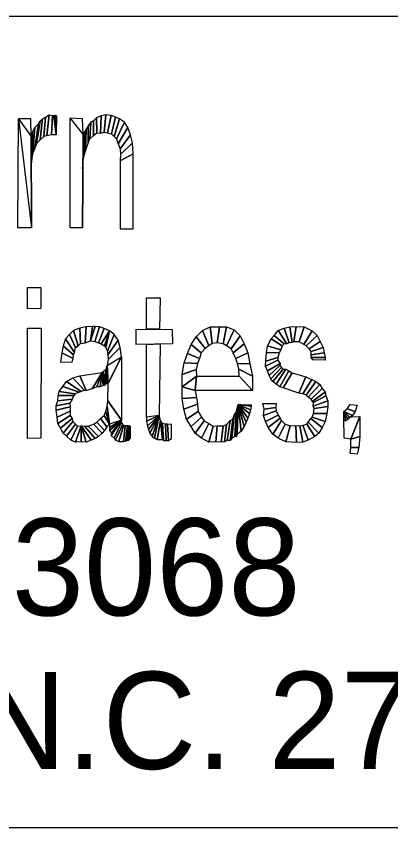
# Model space of a CAD drawing. Extents: x 578158 to 582505, y -54320 to -53220.
# Drawn here: x 579757.4 to 579778.85, y -53316.14 to -53269.66 of the extents above; entities that cross this region are included whole.
import ezdxf

# ---------------------------------------------------------------- set-up
doc = ezdxf.new("R2010")
doc.units = 0
for name, color, linetype in [('Old_Level_2', 7, 'Continuous'), ('Sheet Profile CELL', 7, 'Continuous'), ('Sheet Summary CELL', 7, 'Continuous')]:
    doc.layers.add(name, color=color, linetype=linetype)

msp = doc.modelspace()

# ---------------------------------------------------------------- linework, layer by layer
at = {"layer": 'Old_Level_2'}
for points in [[(579758.978, -53276.554), (579759.068, -53275.443), (579759.278, -53275.308), (579759.142, -53276.509)], [(579759.142, -53276.509), (579759.278, -53275.308), (579759.473, -53275.353), (579759.413, -53276.449)], [(579759.413, -53276.449), (579759.473, -53275.353), (579759.548, -53275.353), (579759.682, -53276.449)], [(579759.682, -53276.449), (579759.548, -53275.353), (579759.653, -53275.323), (579759.682, -53276.449)], [(579759.682, -53276.449), (579759.653, -53275.323), (579759.698, -53275.369), (579759.682, -53276.449)], [(579762.218, -53276.359), (579762.263, -53275.369), (579761.993, -53275.488), (579762.008, -53276.343)], [(579762.428, -53276.298), (579762.518, -53275.308), (579762.263, -53275.369), (579762.218, -53276.359)], [(579762.623, -53276.343), (579762.833, -53275.353), (579762.518, -53275.308), (579762.428, -53276.298)], [(579762.848, -53276.403), (579763.073, -53275.443), (579762.833, -53275.353), (579762.623, -53276.343)], [(579757.478, -53281.788), (579757.522, -53275.533), (579758.258, -53276.554), (579758.273, -53281.788)], [(579758.273, -53281.788), (579758.258, -53276.554), (579758.228, -53275.533), (579757.522, -53275.533)], [(579758.348, -53277.483), (579758.453, -53276.043), (579758.663, -53275.834), (579758.453, -53277.214)], [(579758.453, -53277.214), (579758.663, -53275.834), (579758.768, -53275.668), (579758.558, -53276.959)], [(579758.558, -53276.959), (579758.768, -53275.668), (579758.903, -53275.533), (579758.768, -53276.734)], [(579758.768, -53276.734), (579758.903, -53275.533), (579759.068, -53275.443), (579758.978, -53276.554)], [(579760.493, -53281.774), (579760.493, -53275.503), (579761.228, -53276.449), (579761.198, -53281.788)], [(579761.183, -53275.533), (579760.493, -53275.503), (579761.228, -53276.449)], [(579761.603, -53276.689), (579761.662, -53275.729), (579761.513, -53275.938), (579761.513, -53276.928)], [(579761.828, -53276.494), (579761.813, -53275.654), (579761.662, -53275.729), (579761.603, -53276.689)], [(579762.008, -53276.343), (579761.993, -53275.488), (579761.813, -53275.654), (579761.828, -53276.494)], [(579763.013, -53276.554), (579763.313, -53275.533), (579763.073, -53275.443), (579762.848, -53276.403)], [(579763.133, -53276.689), (579763.598, -53275.729), (579763.313, -53275.533), (579763.013, -53276.554)], [(579763.238, -53276.973), (579763.778, -53276.043), (579763.598, -53275.729), (579763.133, -53276.689)], [(579758.258, -53278.174), (579758.258, -53276.554), (579758.333, -53276.298), (579758.288, -53277.769)], [(579758.288, -53277.769), (579758.333, -53276.298), (579758.453, -53276.043), (579758.348, -53277.483)], [(579761.243, -53277.769), (579761.318, -53276.269), (579761.228, -53276.449), (579761.198, -53278.399)], [(579761.363, -53277.378), (579761.408, -53276.134), (579761.318, -53276.269), (579761.243, -53277.769)], [(579761.513, -53276.928), (579761.513, -53275.938), (579761.408, -53276.134), (579761.363, -53277.378)], [(579763.343, -53277.259), (579763.943, -53276.449), (579763.778, -53276.043), (579763.238, -53276.973)], [(579758.258, -53276.554), (579758.258, -53276.554), (579758.258, -53278.174), (579758.273, -53281.788)], [(579761.228, -53276.449), (579761.228, -53276.449), (579761.198, -53278.399), (579761.198, -53281.788)], [(579763.358, -53277.589), (579764.048, -53276.914), (579763.943, -53276.449), (579763.343, -53277.259)], [(579763.343, -53277.949), (579764.093, -53277.543), (579764.048, -53276.914), (579763.358, -53277.589)], [(579763.343, -53281.833), (579764.093, -53281.833), (579764.093, -53277.543), (579763.343, -53277.949)], [(579758.033, -53285.194), (579758.798, -53285.194), (579758.798, -53286.409), (579758.048, -53286.423)], [(579764.858, -53285.793), (579765.638, -53285.793), (579765.608, -53287.593), (579764.858, -53287.593)], [(579761.348, -53288.358), (579761.408, -53287.443), (579761.033, -53287.534), (579761.078, -53288.403)], [(579761.648, -53288.254), (579761.768, -53287.429), (579761.408, -53287.443), (579761.348, -53288.358)], [(579761.888, -53288.299), (579762.158, -53287.443), (579761.918, -53287.429), (579761.648, -53288.254)], [(579761.648, -53288.254), (579761.918, -53287.429), (579761.768, -53287.429), (579761.648, -53288.254)], [(579762.113, -53288.358), (579762.428, -53287.548), (579762.158, -53287.443), (579761.888, -53288.299)], [(579768.502, -53287.458), (579768.608, -53288.403), (579768.428, -53288.538), (579768.068, -53287.669)], [(579769.028, -53287.443), (579768.908, -53288.358), (579768.608, -53288.403), (579768.502, -53287.458)], [(579769.433, -53287.458), (579769.238, -53288.434), (579768.908, -53288.358), (579769.028, -53287.443)], [(579769.868, -53287.623), (579769.433, -53288.538), (579769.238, -53288.434), (579769.433, -53287.458)], [(579773.063, -53287.443), (579773.198, -53288.343), (579773.033, -53288.358), (579772.733, -53287.534)], [(579773.423, -53287.429), (579773.288, -53288.313), (579773.198, -53288.343), (579773.063, -53287.443)], [(579773.888, -53287.458), (579773.603, -53288.313), (579773.288, -53288.313), (579773.423, -53287.429)], [(579774.338, -53287.683), (579773.873, -53288.463), (579773.603, -53288.313), (579773.888, -53287.458)], [(579758.048, -53287.534), (579758.828, -53287.534), (579758.798, -53293.834), (579758.048, -53293.848)], [(579760.793, -53288.643), (579760.448, -53287.894), (579760.222, -53288.133), (579760.733, -53288.929)], [(579760.942, -53288.538), (579760.673, -53287.669), (579760.448, -53287.894), (579760.793, -53288.643)], [(579761.078, -53288.403), (579761.033, -53287.534), (579760.673, -53287.669), (579760.942, -53288.538)], [(579762.263, -53288.434), (579762.728, -53287.683), (579762.428, -53287.548), (579762.113, -53288.358)], [(579762.443, -53288.538), (579762.728, -53287.683), (579762.728, -53287.683), (579762.263, -53288.434)], [(579762.518, -53288.643), (579762.728, -53287.683), (579762.728, -53287.683), (579762.443, -53288.538)], [(579762.623, -53288.853), (579763.013, -53287.894), (579762.728, -53287.683), (579762.518, -53288.643)], [(579762.638, -53289.049), (579763.238, -53288.223), (579763.013, -53287.894), (579762.623, -53288.853)], [(579764.273, -53288.463), (579764.273, -53287.593), (579766.328, -53287.609), (579766.342, -53288.434)], [(579768.068, -53287.669), (579768.428, -53288.538), (579768.218, -53288.689), (579767.708, -53288.029)], [(579770.213, -53287.969), (579769.703, -53288.703), (579769.433, -53288.538), (579769.868, -53287.623)], [(579772.163, -53287.939), (579772.733, -53288.434), (579772.628, -53288.538), (579771.998, -53288.133)], [(579772.403, -53287.669), (579772.898, -53288.434), (579772.733, -53288.434), (579772.163, -53287.939)], [(579772.733, -53287.534), (579773.033, -53288.358), (579772.898, -53288.434), (579772.403, -53287.669)], [(579774.622, -53287.953), (579774.008, -53288.538), (579773.873, -53288.463), (579774.338, -53287.683)], [(579760.733, -53288.929), (579760.222, -53288.133), (579760.088, -53288.538), (579760.673, -53289.049)], [(579762.668, -53289.319), (579763.343, -53288.643), (579763.238, -53288.223), (579762.638, -53289.049)], [(579767.708, -53288.029), (579768.218, -53288.689), (579767.993, -53288.943), (579767.408, -53288.463)], [(579770.453, -53288.434), (579769.823, -53288.943), (579769.703, -53288.703), (579770.213, -53287.969)], [(579771.998, -53288.133), (579772.628, -53288.538), (579772.553, -53288.763), (579771.788, -53288.538)], [(579774.802, -53288.299), (579774.173, -53288.703), (579774.008, -53288.538), (579774.622, -53287.953)], [(579774.982, -53288.643), (579774.278, -53288.869), (579774.173, -53288.703), (579774.802, -53288.299)], [(579760.673, -53289.049), (579760.088, -53288.538), (579759.998, -53288.943), (579760.658, -53289.258)], [(579762.608, -53289.663), (579763.418, -53289.168), (579763.343, -53288.643), (579762.668, -53289.319)], [(579764.858, -53288.463), (579765.638, -53288.434), (579765.578, -53292.529), (579764.858, -53292.633)], [(579767.408, -53288.463), (579767.993, -53288.943), (579767.888, -53289.258), (579767.198, -53288.974)], [(579770.662, -53288.943), (579769.973, -53289.274), (579769.823, -53288.943), (579770.453, -53288.434)], [(579771.788, -53288.538), (579772.553, -53288.763), (579772.448, -53288.943), (579771.728, -53288.929)], [(579775.028, -53288.943), (579774.293, -53289.049), (579774.278, -53288.869), (579774.982, -53288.643)], [(579760.658, -53289.258), (579759.998, -53288.943), (579759.938, -53289.483), (579760.598, -53289.454)], [(579762.668, -53290.683), (579762.608, -53289.663), (579763.418, -53289.168)], [(579763.433, -53292.799), (579762.638, -53291.688), (579762.668, -53290.683), (579763.418, -53289.168)], [(579767.198, -53288.974), (579767.888, -53289.258), (579767.768, -53289.559), (579767.018, -53289.514)], [(579770.783, -53289.573), (579770.063, -53289.559), (579769.973, -53289.274), (579770.662, -53288.943)], [(579771.698, -53289.423), (579772.373, -53289.213), (579772.373, -53289.363), (579771.668, -53289.708)], [(579771.728, -53288.929), (579772.448, -53288.943), (579772.373, -53289.213), (579771.698, -53289.423)], [(579775.088, -53289.213), (579774.293, -53289.213), (579774.293, -53289.049), (579775.028, -53288.943)], [(579775.088, -53289.363), (579774.383, -53289.334), (579774.293, -53289.213), (579775.088, -53289.213)], [(579762.608, -53290.683), (579762.548, -53289.874), (579762.608, -53289.663), (579762.668, -53290.683)], [(579767.018, -53289.514), (579767.768, -53289.559), (579767.708, -53289.888), (579766.898, -53290.174)], [(579770.918, -53290.279), (579770.153, -53289.874), (579770.063, -53289.559), (579770.783, -53289.573)], [(579771.668, -53289.708), (579772.373, -53289.363), (579772.508, -53289.559), (579771.788, -53289.963)], [(579771.788, -53289.963), (579772.508, -53289.559), (579772.493, -53289.663), (579771.878, -53290.234)], [(579771.878, -53290.234), (579772.493, -53289.663), (579772.583, -53289.783), (579771.983, -53290.428)], [(579771.983, -53290.428), (579772.583, -53289.783), (579772.688, -53289.874), (579772.088, -53290.579)], [(579761.302, -53291.089), (579760.628, -53290.369), (579761.033, -53290.248), (579761.408, -53291.089)], [(579761.408, -53291.089), (579761.033, -53290.248), (579762.323, -53290.068), (579761.753, -53290.999)], [(579761.753, -53290.999), (579762.323, -53290.068), (579762.323, -53290.068), (579762.008, -53290.878)], [(579762.008, -53290.878), (579762.323, -53290.068), (579762.323, -53290.068), (579762.202, -53290.878)], [(579762.202, -53290.878), (579762.323, -53290.068), (579762.323, -53290.068), (579762.368, -53290.819)], [(579762.368, -53290.819), (579762.323, -53290.068), (579762.398, -53289.994), (579762.458, -53290.803)], [(579762.458, -53290.803), (579762.398, -53289.994), (579762.548, -53289.874), (579762.458, -53290.803)], [(579762.458, -53290.803), (579762.548, -53289.874), (579762.548, -53289.874), (579762.518, -53290.743)], [(579762.518, -53290.743), (579762.548, -53289.874), (579762.548, -53289.874), (579762.608, -53290.683)], [(579766.898, -53290.174), (579767.708, -53289.888), (579767.723, -53290.279), (579766.898, -53290.878)], [(579770.918, -53291.103), (579770.168, -53290.279), (579770.153, -53289.874), (579770.918, -53290.279)], [(579772.088, -53290.579), (579772.688, -53289.874), (579772.838, -53289.874), (579772.282, -53290.743)], [(579772.282, -53290.743), (579772.838, -53289.874), (579773.002, -53289.963), (579772.493, -53290.894)], [(579772.493, -53290.894), (579773.002, -53289.963), (579773.198, -53290.083), (579772.688, -53290.939)], [(579772.688, -53290.939), (579773.198, -53290.083), (579773.978, -53290.309), (579773.588, -53291.254)], [(579761.003, -53291.193), (579760.058, -53290.863), (579760.283, -53290.579), (579761.108, -53291.148)], [(579761.108, -53291.148), (579760.283, -53290.579), (579760.628, -53290.369), (579761.302, -53291.089)], [(579766.898, -53290.878), (579767.723, -53290.279), (579767.648, -53291.089)], [(579767.648, -53291.089), (579767.723, -53290.279), (579770.168, -53290.279), (579770.918, -53291.103)], [(579773.588, -53291.254), (579773.978, -53290.309), (579774.323, -53290.473), (579773.813, -53291.283)], [(579773.813, -53291.283), (579774.323, -53290.473), (579774.563, -53290.579), (579774.008, -53291.373)], [(579774.008, -53291.373), (579774.563, -53290.579), (579774.788, -53290.759), (579774.113, -53291.479)], [(579760.688, -53291.389), (579759.803, -53291.389), (579759.862, -53291.148), (579760.778, -53291.283)], [(579760.778, -53291.283), (579759.862, -53291.148), (579760.058, -53290.863), (579761.003, -53291.193)], [(579766.898, -53290.878), (579767.648, -53291.089), (579767.723, -53291.494), (579766.898, -53291.553)], [(579774.113, -53291.479), (579774.788, -53290.759), (579774.908, -53290.983), (579774.278, -53291.598)], [(579774.278, -53291.598), (579774.908, -53290.983), (579775.088, -53291.193), (579774.353, -53291.719)], [(579774.353, -53291.719), (579775.088, -53291.193), (579775.133, -53291.403), (579774.413, -53291.794)], [(579760.463, -53291.823), (579759.682, -53291.974), (579759.773, -53291.688), (579760.598, -53291.598)], [(579760.598, -53291.598), (579759.773, -53291.688), (579759.803, -53291.389), (579760.688, -53291.389)], [(579766.898, -53291.553), (579767.723, -53291.494), (579767.768, -53291.883), (579767.003, -53292.169)], [(579774.413, -53291.794), (579775.133, -53291.403), (579775.238, -53291.688), (579774.398, -53292.003)], [(579760.493, -53292.034), (579759.682, -53292.228), (579759.682, -53291.974), (579760.463, -53291.823)], [(579760.493, -53292.289), (579759.743, -53292.619), (579759.682, -53292.228), (579760.493, -53292.034)], [(579762.608, -53292.019), (579762.728, -53293.023), (579762.728, -53293.023), (579762.518, -53292.303)], [(579762.638, -53291.688), (579763.433, -53292.799), (579762.728, -53293.023), (579762.608, -53292.019)], [(579767.003, -53292.169), (579767.768, -53291.883), (579767.813, -53292.303), (579767.138, -53292.739)], [(579769.913, -53293.729), (579769.988, -53292.334), (579770.048, -53292.109), (579769.988, -53293.743)], [(579769.988, -53293.743), (579770.048, -53292.109), (579770.108, -53291.899), (579770.048, -53293.609)], [(579770.048, -53293.609), (579770.108, -53291.899), (579770.108, -53291.899), (579770.273, -53293.429)], [(579770.842, -53292.003), (579770.108, -53291.899), (579770.108, -53291.899), (579770.858, -53291.913)], [(579770.813, -53292.199), (579770.108, -53291.899), (579770.108, -53291.899), (579770.842, -53292.003)], [(579770.753, -53292.408), (579770.108, -53291.899), (579770.108, -53291.899), (579770.813, -53292.199)], [(579770.662, -53292.678), (579770.108, -53291.899), (579770.108, -53291.899), (579770.753, -53292.408)], [(579770.573, -53292.919), (579770.108, -53291.899), (579770.108, -53291.899), (579770.662, -53292.678)], [(579770.453, -53293.159), (579770.108, -53291.899), (579770.108, -53291.899), (579770.573, -53292.919)], [(579770.273, -53293.429), (579770.108, -53291.899), (579770.108, -53291.899), (579770.453, -53293.159)], [(579772.268, -53292.063), (579771.593, -53292.169), (579771.518, -53291.839), (579772.282, -53291.839)], [(579772.282, -53292.259), (579771.548, -53292.529), (579771.593, -53292.169), (579772.268, -53292.063)], [(579774.398, -53292.003), (579775.238, -53291.688), (579775.238, -53292.019), (579774.458, -53292.123)], [(579774.458, -53292.123), (579775.238, -53292.019), (579775.178, -53292.408), (579774.413, -53292.423)], [(579776.513, -53291.899), (579776.918, -53291.929), (579776.798, -53292.303), (579776.348, -53292.138)], [(579760.493, -53292.529), (579759.773, -53292.979), (579759.743, -53292.619), (579760.493, -53292.289)], [(579760.598, -53292.709), (579759.938, -53293.263), (579759.773, -53292.979), (579760.493, -53292.529)], [(579762.428, -53292.529), (579762.728, -53293.023), (579762.578, -53293.173), (579762.218, -53292.709)], [(579762.518, -53292.303), (579762.728, -53293.023), (579762.728, -53293.023), (579762.428, -53292.529)], [(579764.918, -53293.114), (579765.578, -53292.529), (579765.578, -53292.529), (579764.858, -53292.858)], [(579764.858, -53292.858), (579765.578, -53292.529), (579765.578, -53292.529), (579764.858, -53292.633)], [(579764.963, -53293.323), (579765.578, -53292.529), (579765.578, -53292.529), (579764.918, -53293.114)], [(579765.038, -53293.549), (579765.578, -53292.529), (579765.578, -53292.529), (579764.963, -53293.323)], [(579765.188, -53293.729), (579765.578, -53292.529), (579765.578, -53292.529), (579765.038, -53293.549)], [(579765.323, -53293.834), (579765.578, -53292.529), (579765.578, -53292.529), (579765.188, -53293.729)], [(579765.473, -53293.909), (579765.653, -53292.813), (579765.578, -53292.529), (579765.323, -53293.834)], [(579767.138, -53292.739), (579767.813, -53292.303), (579768.008, -53292.619), (579767.408, -53293.159)], [(579769.643, -53293.954), (579769.808, -53292.739), (579769.883, -53292.514), (579769.748, -53293.834)], [(579769.748, -53293.834), (579769.883, -53292.514), (579769.988, -53292.334), (579769.913, -53293.729)], [(579772.388, -53292.514), (579771.668, -53292.874), (579771.548, -53292.529), (579772.282, -53292.259)], [(579772.508, -53292.678), (579771.833, -53293.218), (579771.668, -53292.874), (579772.388, -53292.514)], [(579774.413, -53292.423), (579775.178, -53292.408), (579775.088, -53292.874), (579774.353, -53292.619)], [(579776.348, -53292.138), (579776.798, -53292.303), (579776.663, -53292.529), (579776.153, -53292.303)], [(579776.153, -53292.303), (579776.663, -53292.529), (579776.498, -53292.649), (579776.153, -53292.303)], [(579776.153, -53292.303), (579776.498, -53292.649), (579776.378, -53292.754), (579776.153, -53292.303)], [(579776.153, -53292.303), (579776.378, -53292.754), (579776.273, -53292.843), (579776.153, -53292.303)], [(579776.153, -53292.303), (579776.273, -53292.843), (579776.153, -53292.843), (579776.153, -53292.303)], [(579776.153, -53292.619), (579777.083, -53292.588), (579776.558, -53293.879), (579776.168, -53293.834)], [(579776.558, -53293.879), (579777.083, -53292.588), (579777.068, -53293.729)], [(579760.628, -53292.874), (579760.088, -53293.549), (579759.938, -53293.263), (579760.598, -53292.709)], [(579760.793, -53293.023), (579760.283, -53293.713), (579760.088, -53293.549), (579760.628, -53292.874)], [(579760.898, -53293.143), (579760.523, -53293.938), (579760.283, -53293.713), (579760.793, -53293.023)], [(579761.813, -53293.023), (579762.323, -53293.533), (579762.113, -53293.729), (579761.513, -53293.143)], [(579762.008, -53292.919), (579762.458, -53293.383), (579762.323, -53293.533), (579761.813, -53293.023)], [(579762.218, -53292.709), (579762.578, -53293.173), (579762.458, -53293.383), (579762.008, -53292.919)], [(579762.848, -53293.533), (579763.433, -53292.799), (579763.433, -53292.799), (579762.728, -53293.383)], [(579762.728, -53293.218), (579763.433, -53292.799), (579763.433, -53292.799), (579762.728, -53293.023)], [(579762.728, -53293.383), (579763.433, -53292.799), (579763.433, -53292.799), (579762.728, -53293.218)], [(579762.833, -53293.668), (579763.433, -53292.799), (579763.433, -53292.799), (579762.848, -53293.533)], [(579762.998, -53293.834), (579763.418, -53292.919), (579763.433, -53292.799), (579762.833, -53293.668)], [(579763.088, -53293.938), (579763.493, -53293.023), (579763.418, -53292.919), (579762.998, -53293.834)], [(579763.268, -53294.014), (579763.538, -53293.114), (579763.493, -53293.023), (579763.088, -53293.938)], [(579765.773, -53293.909), (579765.653, -53292.813), (579765.653, -53292.813), (579765.473, -53293.909)], [(579765.833, -53293.954), (579765.773, -53292.979), (579765.653, -53292.813), (579765.773, -53293.909)], [(579765.982, -53293.954), (579765.938, -53293.023), (579765.773, -53292.979), (579765.833, -53293.954)], [(579766.118, -53293.954), (579766.058, -53293.023), (579765.938, -53293.023), (579765.982, -53293.954)], [(579766.283, -53293.848), (579766.283, -53293.038), (579766.058, -53293.023), (579766.118, -53293.954)], [(579767.408, -53293.159), (579768.008, -53292.619), (579768.158, -53292.829), (579767.648, -53293.533)], [(579767.648, -53293.533), (579768.158, -53292.829), (579768.428, -53292.979), (579768.008, -53293.834)], [(579768.008, -53293.834), (579768.428, -53292.979), (579768.682, -53293.143), (579768.428, -53294.059)], [(579769.133, -53294.059), (579769.238, -53293.114), (579769.433, -53293.038), (579769.328, -53294.028)], [(579769.328, -53294.028), (579769.433, -53293.038), (579769.643, -53292.813), (579769.478, -53293.954)], [(579769.478, -53293.954), (579769.643, -53292.813), (579769.808, -53292.739), (579769.643, -53293.954)], [(579772.583, -53292.813), (579772.088, -53293.594), (579771.833, -53293.218), (579772.508, -53292.678)], [(579772.793, -53293.023), (579772.388, -53293.834), (579772.088, -53293.594), (579772.583, -53292.813)], [(579773.093, -53293.114), (579772.838, -53294.028), (579772.388, -53293.834), (579772.793, -53293.023)], [(579774.038, -53293.023), (579774.488, -53293.729), (579774.113, -53293.938), (579773.813, -53293.083)], [(579774.113, -53292.919), (579774.728, -53293.533), (579774.488, -53293.729), (579774.038, -53293.023)], [(579774.262, -53292.709), (579774.923, -53293.218), (579774.728, -53293.533), (579774.113, -53292.919)], [(579774.353, -53292.619), (579775.088, -53292.874), (579774.923, -53293.218), (579774.262, -53292.709)], [(579761.108, -53293.114), (579760.793, -53294.059), (579760.523, -53293.938), (579760.898, -53293.143)], [(579761.108, -53293.114), (579761.108, -53294.028), (579760.793, -53294.059), (579761.108, -53293.114)], [(579761.108, -53293.114), (579761.408, -53294.059), (579761.108, -53294.028), (579761.108, -53293.114)], [(579761.108, -53293.114), (579761.693, -53293.938), (579761.408, -53294.059), (579761.108, -53293.114)], [(579761.302, -53293.143), (579761.918, -53293.848), (579761.693, -53293.938), (579761.108, -53293.114)], [(579761.513, -53293.143), (579762.113, -53293.729), (579761.918, -53293.848), (579761.302, -53293.143)], [(579763.538, -53294.014), (579763.642, -53293.114), (579763.538, -53293.114), (579763.268, -53294.014)], [(579763.658, -53293.999), (579763.763, -53293.114), (579763.642, -53293.114), (579763.538, -53294.014)], [(579763.748, -53293.954), (579763.808, -53293.114), (579763.763, -53293.114), (579763.658, -53293.999)], [(579763.838, -53293.938), (579763.838, -53293.114), (579763.808, -53293.114), (579763.748, -53293.954)], [(579763.943, -53293.834), (579763.943, -53293.143), (579763.838, -53293.114), (579763.838, -53293.938)], [(579768.428, -53294.059), (579768.682, -53293.143), (579768.908, -53293.114), (579768.833, -53294.028)], [(579768.833, -53294.028), (579768.908, -53293.114), (579769.238, -53293.114), (579769.133, -53294.059)], [(579773.408, -53293.099), (579773.438, -53294.073), (579772.838, -53294.028), (579773.093, -53293.114)], [(579773.633, -53293.114), (579773.813, -53294.059), (579773.438, -53294.073), (579773.408, -53293.099)], [(579773.813, -53293.083), (579774.113, -53293.938), (579773.813, -53294.059), (579773.633, -53293.114)], [(579776.558, -53293.879), (579777.068, -53293.729), (579777.023, -53294.359), (579776.558, -53294.359)], [(579776.558, -53294.359), (579777.023, -53294.359), (579776.918, -53294.748), (579776.513, -53294.703)]]:
    msp.add_lwpolyline(points, close=True, dxfattribs=at)
at = {"layer": 'Sheet Profile CELL'}
msp.add_line((579624.937, -53269.662), (579824.937, -53269.662), dxfattribs=at)
at = {"layer": 'Sheet Summary CELL'}
msp.add_lwpolyline([(579624.887, -53269.662), (579824.937, -53269.662), (579824.937, -53316.141), (579624.887, -53316.141)], close=True, dxfattribs=at)

# ---------------------------------------------------------------- texts
at = {"layer": 'Old_Level_2'}
for s, p in [('P.O. BOX 33068', (579718.298, -53303.989)), ('RALEIGH, N.C. 27636-3068', (579718.133, -53312.779))]:
    msp.add_text(s, height=5.56001, rotation=0.0107, dxfattribs=at).set_placement(p)

doc.saveas('drawing.dxf')
